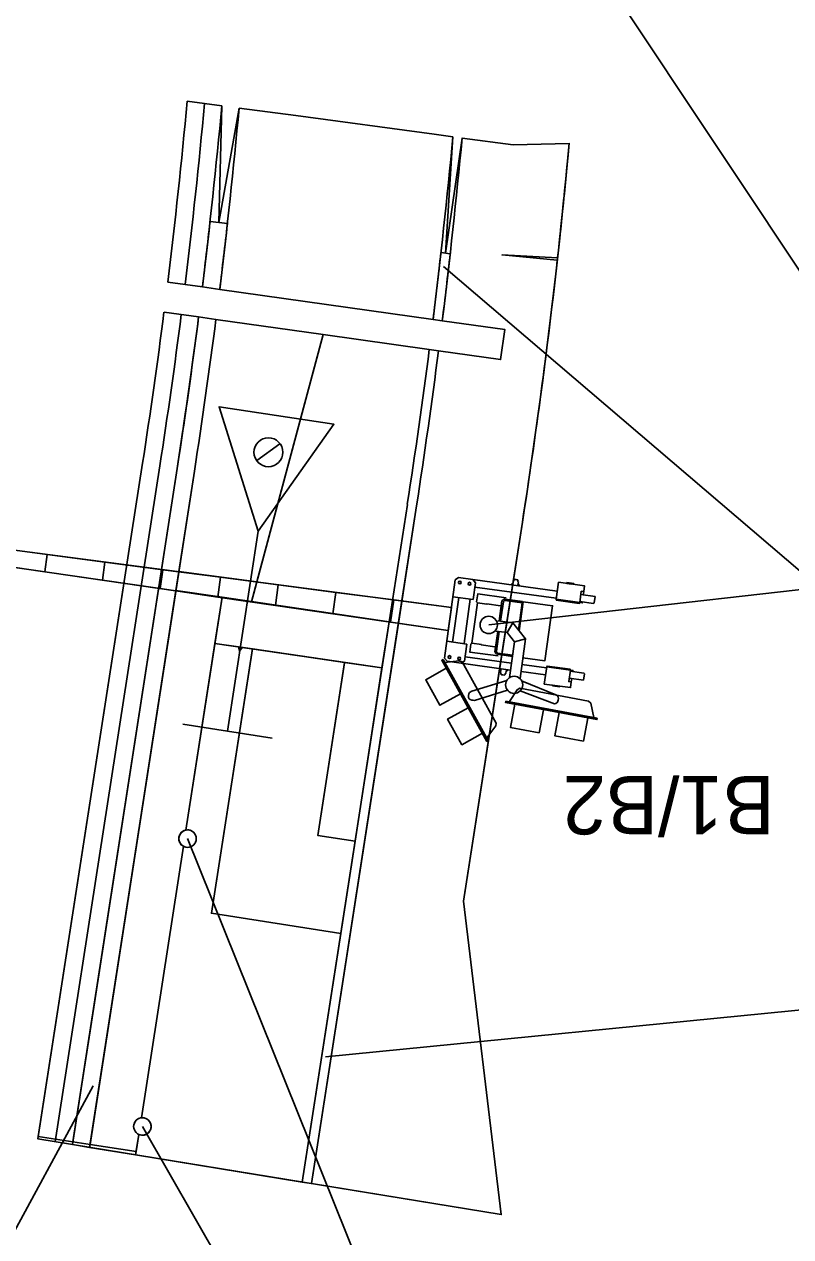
# Model space of a CAD drawing. Extents: x -728547 to -728179, y -1073068 to -1072839.
# Drawn here: x -728503.68 to -728497.09, y -1073053.69 to -1073043.28 of the extents above; entities that cross this region are included whole.
import ezdxf

# ---------------------------------------------------------------- set-up
doc = ezdxf.new("R2010")
doc.units = 0
for name, color, linetype in [('_NOR-návrh tenká', 7, 'Continuous'), ('_NOR-popis', 7, 'Continuous'), ('_NOR-VDZ', 7, 'Continuous'), ('_NOR-šraf_+6', 7, 'Continuous'), ('_NOR-šraf_bezbariéra', 7, 'Continuous'), ('_NOR-šraf_chodník', 7, 'Continuous'), ('_NOR-šraf_signální pás', 7, 'Continuous'), ('_NOR-šraf_varovný pás', 7, 'Continuous'), ('_NOR-šraf_vozovka', 7, 'Continuous'), ('_NOR-šraf_zeleň', 7, 'Continuous'), ('KOS_kabelová trasa', 7, 'Continuous'), ('KOS_nové prvky PZZ', 7, 'Continuous'), ('KTA_PZZ rušené', 7, 'Continuous')]:
    doc.layers.add(name, color=color, linetype=linetype)

# ---------------------------------------------------------------- blocks, each defined once
blk = doc.blocks.new('Závora B')
for p, q in [((0.614, 0.452), (0.676, 0.452)), ((0.676, 0.452), (0.676, 0.445)), ((-0.312, 0.367), (-0.338, 0.343)), ((-0.338, 0.343), (-0.338, -0.335)), ((-0.312, 0.367), (-0.189, 0.367)), ((-0.189, 0.367), (0.541, 0.367)), ((-0.189, 0.367), (-0.163, 0.343)), ((0.769, 0.395), (0.769, 0.367)), ((-0.163, 0.306), (0.541, 0.306)), ((0.259, 0.227), (0.259, -0.009)), ((-6.838, 0.058), (-0.338, 0.104)), ((-0.338, 0.197), (-0.163, 0.197)), ((-0.338, -0.096), (-0.338, 0.104)), ((-0.338, -0.096), (-0.338, 0.104)), ((-0.338, -0.096), (-0.338, 0.104)), ((-0.338, -0.096), (-0.338, 0.104)), ((-0.338, -0.096), (-0.338, 0.104)), ((-0.338, -0.096), (-0.338, 0.104)), ((-0.338, -0.096), (-0.338, 0.104)), ((-0.338, -0.096), (-0.338, 0.104)), ((-0.288, 0.197), (-0.288, -0.188)), ((-0.187, 0.197), (-0.187, -0.188)), ((-0.123, 0.174), (-0.123, -0.176)), ((-6.838, -0.049), (-6.838, 0.058)), ((0.202, 0.045), (0.165, -0.044)), ((-6.838, -0.049), (-0.338, -0.096)), ((0.329, -0.076), (0.239, -0.114)), ((-0.338, -0.188), (-0.163, -0.188)), ((-0.163, -0.188), (-0.163, -0.335)), ((-0.163, -0.298), (0.239, -0.298)), ((0.329, -0.298), (0.541, -0.298)), ((-0.347, -0.347), (0.132, -0.984)), ((-0.312, -0.358), (-0.338, -0.335)), ((-0.189, -0.358), (-0.163, -0.335)), ((-0.189, -0.358), (0.239, -0.358)), ((0.329, -0.358), (0.541, -0.358)), ((0.769, -0.387), (0.769, -0.358)), ((0.653, -0.515), (0.345, -0.438)), ((0.614, -0.443), (0.676, -0.443)), ((0.676, -0.443), (0.676, -0.437)), ((-0.033, -0.659), (0.235, -0.532)), ((0.236, -0.627), (1.032, -0.665))]:
    blk.add_line(p, q)
for points in [[(0.179, 0.418), (0.166, 0.418), (0.165, 0.411), (0.16, 0.411), (0.16, 0.401), (0.157, 0.401), (0.157, 0.378), (0.148, 0.378), (0.148, 0.372), (0.148, 0.367)], [(0.179, 0.418), (0.192, 0.418), (0.193, 0.411), (0.197, 0.411), (0.197, 0.401), (0.201, 0.401), (0.201, 0.378), (0.21, 0.378), (0.21, 0.372), (0.21, 0.367)], [(0.542, 0.445), (0.542, 0.297), (0.747, 0.297), (0.747, 0.395), (0.769, 0.395), (0.769, 0.445), (0.542, 0.445)], [(0.614, 0.452), (0.614, 0.445)], [(0.655, 0.445), (0.614, 0.445)], [(-0.163, 0.343), (-0.163, 0.197)], [(0.872, 0.367), (0.747, 0.367)], [(0.872, 0.367), (0.872, 0.312), (0.866, 0.306), (0.747, 0.306)], [(0.116, 0.251), (-0.13, 0.251), (-0.13, 0.182), (-0.123, 0.174), (-0.04, 0.174), (-0.04, 0.177), (0.077, 0.177), (0.078, 0.181), (0.084, 0.181)], [(0.259, 0.238), (0.109, 0.238), (0.098, 0.236), (0.092, 0.23), (0.086, 0.223), (0.084, 0.219), (0.084, 0.045)], [(0.259, 0.238), (0.259, 0.227), (0.11, 0.227), (0.106, 0.225), (0.102, 0.222), (0.098, 0.218), (0.097, 0.213), (0.097, 0.045)], [(0.265, 0.238), (0.52, 0.238), (0.52, -0.239), (0.329, -0.239)], [(0.265, -0.015), (0.265, 0.238)], [(0.545, 0.297), (0.545, 0.289), (0.745, 0.289), (0.745, 0.297)], [(0.747, 0.297), (0.77, 0.297), (0.77, 0.306)], [(-0.338, -0.096), (-0.338, 0.104), (-0.838, 0.101), (-0.838, -0.092), (-0.338, -0.096)], [(-6.338, -0.053), (-6.338, 0.061), (-6.838, 0.058), (-6.838, -0.049), (-6.338, -0.053)], [(-5.838, -0.057), (-5.838, 0.065), (-6.338, 0.061), (-6.338, -0.053), (-5.838, -0.057)], [(-5.338, -0.06), (-5.338, 0.068), (-5.838, 0.065), (-5.838, -0.057), (-5.338, -0.06)], [(-4.838, -0.064), (-4.838, 0.072), (-5.338, 0.068), (-5.338, -0.06), (-4.838, -0.064)], [(-4.338, -0.067), (-4.338, 0.076), (-4.838, 0.072), (-4.838, -0.064), (-4.338, -0.067)], [(-3.838, -0.071), (-3.838, 0.079), (-4.338, 0.076), (-4.338, -0.067), (-3.838, -0.071)], [(-3.338, -0.074), (-3.338, 0.083), (-3.838, 0.079), (-3.838, -0.071), (-3.338, -0.074)], [(-2.838, -0.078), (-2.838, 0.086), (-3.338, 0.083), (-3.338, -0.074), (-2.838, -0.078)], [(-2.338, -0.082), (-2.338, 0.09), (-2.838, 0.086), (-2.838, -0.078), (-2.338, -0.082)], [(-1.838, -0.085), (-1.838, 0.093), (-2.338, 0.09), (-2.338, -0.082), (-1.838, -0.085)], [(-1.338, -0.089), (-1.338, 0.097), (-1.838, 0.093), (-1.838, -0.085), (-1.338, -0.089)], [(-0.838, -0.092), (-0.838, 0.101), (-1.338, 0.097), (-1.338, -0.089), (-0.838, -0.092)], [(0.071, 0.045), (0.202, 0.045), (0.329, -0.076), (0.329, -0.419)], [(0.066, -0.044), (0.165, -0.044), (0.239, -0.114), (0.239, -0.422)], [(0.239, -0.239), (0.109, -0.239), (0.098, -0.237), (0.092, -0.231), (0.086, -0.224), (0.084, -0.22), (0.084, -0.044)], [(0.239, -0.228), (0.11, -0.228), (0.106, -0.226), (0.102, -0.223), (0.098, -0.219), (0.097, -0.214), (0.097, -0.044)], [(0.116, -0.253), (-0.13, -0.253), (-0.13, -0.184), (-0.123, -0.176), (-0.04, -0.176), (-0.04, -0.178), (0.077, -0.178), (0.078, -0.182), (0.084, -0.182)], [(0.542, -0.437), (0.542, -0.288), (0.747, -0.288), (0.747, -0.387), (0.769, -0.387), (0.769, -0.437), (0.542, -0.437)], [(0.545, -0.288), (0.545, -0.281), (0.745, -0.281), (0.745, -0.288)], [(0.747, -0.288), (0.77, -0.288), (0.77, -0.298)], [(0.872, -0.358), (0.872, -0.304), (0.866, -0.298), (0.747, -0.298)], [(-0.347, -0.347), (-0.358, -0.355), (0.121, -0.992), (0.132, -0.984)], [(-0.329, -0.371), (-0.211, -0.34), (-0.184, -0.346), (0.177, -0.826), (0.178, -0.851), (0.115, -0.962)], [(-0.189, -0.358), (-0.312, -0.358)], [(0.179, -0.409), (0.166, -0.409), (0.165, -0.403), (0.16, -0.403), (0.16, -0.393), (0.157, -0.393), (0.157, -0.37), (0.148, -0.37), (0.148, -0.364), (0.148, -0.358)], [(0.179, -0.409), (0.192, -0.409), (0.193, -0.403), (0.197, -0.403), (0.197, -0.393), (0.201, -0.393), (0.201, -0.37), (0.21, -0.37), (0.21, -0.364), (0.21, -0.358)], [(0.872, -0.358), (0.747, -0.358)], [(-0.311, -0.418), (-0.472, -0.54), (-0.321, -0.74), (-0.16, -0.619)], [(-0.066, -0.584), (0.218, -0.451)], [(0.266, -0.628), (0.318, -0.517), (0.339, -0.501), (0.939, -0.53), (0.959, -0.545), (1.004, -0.664)], [(0.655, -0.437), (0.614, -0.437)], [(0.614, -0.443), (0.614, -0.437)], [(0.652, -0.592), (0.663, -0.589), (0.675, -0.576), (0.679, -0.559), (0.679, -0.544), (0.676, -0.532), (0.667, -0.523), (0.665, -0.52), (0.66, -0.518), (0.653, -0.515)], [(-0.066, -0.584), (-0.084, -0.597), (-0.089, -0.61), (-0.089, -0.625), (-0.087, -0.641), (-0.08, -0.65), (-0.07, -0.655), (-0.055, -0.66), (-0.043, -0.659), (-0.033, -0.659)], [(0.652, -0.592), (0.345, -0.523)], [(0.073, -0.929), (-0.088, -1.05), (-0.239, -0.849), (-0.078, -0.728)], [(0.236, -0.627), (0.235, -0.64), (1.031, -0.678), (1.032, -0.665)], [(0.314, -0.644), (0.305, -0.846), (0.555, -0.858), (0.565, -0.656)], [(0.952, -0.675), (0.942, -0.876), (0.692, -0.864), (0.701, -0.663)]]:
    blk.add_lwpolyline(points)
for centre, radius in [((-0.296, 0.327), 0.0119), ((-0.212, 0.328), 0.0119), ((0, 0), 0.0742), ((-0.296, -0.319), 0.0119), ((-0.212, -0.32), 0.0119), ((0.286, -0.479), 0.0735)]:
    blk.add_circle(centre, radius)

msp = doc.modelspace()

# ---------------------------------------------------------------- linework, layer by layer
at = {"layer": '_NOR-návrh tenká'}
for p, q in [((-728501.98, -1073043.98), (-728502.007, -1073044.983)), ((-728502.007, -1073044.983), (-728501.831, -1073044)), ((-728499.996, -1073044.246), (-728500.059, -1073045.246)), ((-728500.059, -1073045.246), (-728499.917, -1073044.257)), ((-728502.081, -1073044.975), (-728501.932, -1073044.991)), ((-728500.098, -1073045.241), (-728500.019, -1073045.25)), ((-728500.544, -1073048.41), (-728502.374, -1073048.141)), ((-728500.605, -1073048.805), (-728502.04, -1073048.595)), ((-728502.07, -1073050.911), (-728501.718, -1073048.639)), ((-728501.157, -1073050.243), (-728500.927, -1073048.761)), ((-728501.157, -1073050.243), (-728500.836, -1073050.293)), ((-728499.581, -1073053.497), (-728499.904, -1073050.807)), ((-728502.07, -1073050.911), (-728500.958, -1073051.084)), ((-728503.263, -1073052.895), (-728503.559, -1073052.847)), ((-728499.581, -1073053.497), (-728503.263, -1073052.895))]:
    msp.add_line(p, q, dxfattribs=at)
for points in [[(-728501.98, -1073043.98), (-728502.278, -1073043.94)], [(-728502.444, -1073045.494), (-728502.147, -1073045.535)], [(-728502.179, -1073045.793), (-728502.476, -1073045.752)], [(-728502.66, -1073047.048), (-728503.559, -1073052.847)], [(-728502.364, -1073047.094), (-728503.263, -1073052.895)], [(-728502.215, -1073047.117), (-728503.115, -1073052.92)], [(-728500.387, -1073047.401), (-728500.529, -1073048.317)], [(-728500.308, -1073047.413), (-728500.45, -1073048.328)], [(-728499.399, -1073047.554), (-728499.54, -1073048.464)], [(-728500.529, -1073048.317), (-728501.289, -1073053.218)], [(-728500.45, -1073048.328), (-728501.21, -1073053.23)], [(-728499.54, -1073048.464), (-728499.904, -1073050.807)], [(-728502.04, -1073048.595), (-728502.288, -1073050.196)], [(-728502.31, -1073050.336), (-728502.671, -1073052.666)], [(-728502.693, -1073052.808), (-728502.721, -1073052.984)]]:
    msp.add_lwpolyline(points, dxfattribs=at)
for centre in [(-728502.274, -1073050.27), (-728502.662, -1073052.74)]:
    msp.add_circle(centre, 0.075, dxfattribs=at)
for radius, start, end in [(49.7, 352.9936, 354.795), (50, 352.9876, 354.7803), (50.15, 352.9847, 354.7731), (52, 352.9495, 354.687), (52.08, 352.9481, 354.6834), (53, 351.184, 354.726), (49.7, 351.184, 352.6939), (50, 351.184, 352.6897), (50.15, 351.184, 352.6876), (52, 351.184, 352.663), (52.08, 351.184, 352.662)]:
    msp.add_arc((-728551.773, -1073039.431), radius, start, end, dxfattribs=at)
at = {"layer": '_NOR-popis'}
for p, q in [((-728493.062, -1073051.347), (-728499.767, -1073041.269)), ((-728493.062, -1073051.347), (-728500.078, -1073045.361)), ((-728498.014, -1073060.847), (-728502.274, -1073050.27)), ((-728493.062, -1073051.347), (-728501.089, -1073052.144)), ((-728507.112, -1073059.822), (-728503.085, -1073052.392)), ((-728502.662, -1073052.74), (-728498.014, -1073060.847))]:
    msp.add_line(p, q, dxfattribs=at)
at = {"layer": '_NOR-VDZ'}
msp.add_lwpolyline([(-728502.512, -1073047.071), (-728503.411, -1073052.871)], dxfattribs=at)
for start, end in [(352.9906, 354.7876), (351.184, 352.6918)]:
    msp.add_arc((-728551.773, -1073039.431), 49.85, start, end, dxfattribs=at)
at = {"layer": '_NOR-šraf_+6'}
for p, q in [((-728500.019, -1073045.25), (-728500.098, -1073045.241)), ((-728500.166, -1073045.814), (-728500.087, -1073045.825)), ((-728500.119, -1073046.083), (-728500.199, -1073046.072))]:
    msp.add_line(p, q, dxfattribs=at)
msp.add_lwpolyline([(-728500.387, -1073047.401), (-728500.544, -1073048.41), (-728500.605, -1073048.805), (-728500.836, -1073050.293), (-728500.958, -1073051.084), (-728501.289, -1073053.218), (-728501.21, -1073053.231), (-728500.308, -1073047.413)], dxfattribs=at)
for radius, start, end in [(52, 352.9495, 353.5851), (52.08, 352.9481, 353.5851), (52, 351.184, 352.663), (52.08, 351.184, 352.662)]:
    msp.add_arc((-728551.773, -1073039.431), radius, start, end, dxfattribs=at)
at = {"layer": '_NOR-šraf_bezbariéra'}
for p, q in [((-728502.081, -1073044.975), (-728501.932, -1073044.991)), ((-728501.998, -1073045.556), (-728502.147, -1073045.535)), ((-728502.031, -1073045.814), (-728502.179, -1073045.793)), ((-728502.364, -1073047.094), (-728503.259, -1073052.871)), ((-728503.111, -1073052.894), (-728502.215, -1073047.117)), ((-728503.111, -1073052.894), (-728503.259, -1073052.871)), ((-728503.259, -1073052.871), (-728503.111, -1073052.894))]:
    msp.add_line(p, q, dxfattribs=at)
for points in [[(-728503.259, -1073052.871), (-728503.263, -1073052.895), (-728503.229, -1073052.901)], [(-728503.229, -1073052.901), (-728503.115, -1073052.92), (-728503.111, -1073052.894)]]:
    msp.add_lwpolyline(points, dxfattribs=at)
for radius, start, end in [(50, 352.9876, 353.6344), (50.15, 352.9847, 353.6344), (50, 351.184, 352.6897), (50.15, 351.184, 352.6876)]:
    msp.add_arc((-728551.773, -1073039.431), radius, start, end, dxfattribs=at)
at = {"layer": '_NOR-šraf_chodník'}
for p, q in [((-728500.166, -1073045.814), (-728501.998, -1073045.556)), ((-728501.724, -1073048.237), (-728501.111, -1073045.944)), ((-728501.111, -1073045.944), (-728500.199, -1073046.072)), ((-728502.215, -1073047.117), (-728502.349, -1073047.977)), ((-728500.387, -1073047.401), (-728500.544, -1073048.41)), ((-728501.678, -1073048.065), (-728502.349, -1073047.977)), ((-728502.349, -1073047.977), (-728501.678, -1073048.065)), ((-728501.724, -1073048.237), (-728501.678, -1073048.065)), ((-728500.544, -1073048.41), (-728501.724, -1073048.237)), ((-728502.288, -1073050.196), (-728502.04, -1073048.595)), ((-728502.04, -1073048.595), (-728501.838, -1073048.624)), ((-728501.718, -1073048.642), (-728502.07, -1073050.911)), ((-728501.838, -1073048.624), (-728501.827, -1073048.662)), ((-728501.827, -1073048.662), (-728501.838, -1073048.624)), ((-728501.838, -1073048.624), (-728501.804, -1073048.629)), ((-728501.827, -1073048.662), (-728501.804, -1073048.629)), ((-728501.804, -1073048.629), (-728501.827, -1073048.662)), ((-728501.804, -1073048.629), (-728501.718, -1073048.642)), ((-728502.671, -1073052.666), (-728502.31, -1073050.336)), ((-728502.07, -1073050.911), (-728500.958, -1073051.084)), ((-728500.958, -1073051.084), (-728501.289, -1073053.218)), ((-728502.721, -1073052.984), (-728502.693, -1073052.808)), ((-728501.289, -1073053.218), (-728502.721, -1073052.984))]:
    msp.add_line(p, q, dxfattribs=at)
for points in [[(-728501.831, -1073044), (-728501.345, -1073044.065), (-728500.156, -1073044.225), (-728499.996, -1073044.246)], [(-728501.678, -1073048.065), (-728501.111, -1073045.944), (-728502.031, -1073045.814)], [(-728502.349, -1073047.977), (-728502.374, -1073048.141), (-728501.724, -1073048.237)], [(-728501.157, -1073050.243), (-728500.836, -1073050.293), (-728500.605, -1073048.805), (-728500.927, -1073048.758), (-728501.157, -1073050.243)]]:
    msp.add_lwpolyline(points, dxfattribs=at)
for centre, radius, start, end in [((-728551.773, -1073039.431), 50.15, 352.9847, 354.7731), ((-728551.773, -1073039.431), 52, 352.9495, 354.687), ((-728551.773, -1073039.431), 50.15, 351.184, 352.6876), ((-728551.773, -1073039.431), 52, 351.184, 352.663), ((-728502.274, -1073050.27), 0.075, 241.7127, 100.6552), ((-728502.662, -1073052.74), 0.075, 245.3796, 96.9883)]:
    msp.add_arc(centre, radius, start, end, dxfattribs=at)
at = {"layer": '_NOR-šraf_signální pás'}
msp.add_lwpolyline([(-728500.958, -1073051.084), (-728500.836, -1073050.293), (-728501.157, -1073050.243), (-728500.927, -1073048.758), (-728501.718, -1073048.642), (-728502.07, -1073050.911), (-728500.958, -1073051.084)], dxfattribs=at)
at = {"layer": '_NOR-šraf_varovný pás'}
for p, q in [((-728503.111, -1073052.894), (-728502.374, -1073048.141)), ((-728502.374, -1073048.141), (-728501.978, -1073048.199)), ((-728501.978, -1073048.199), (-728502.288, -1073050.196)), ((-728502.31, -1073050.336), (-728502.671, -1073052.666)), ((-728502.693, -1073052.808), (-728502.716, -1073052.955)), ((-728502.716, -1073052.955), (-728503.111, -1073052.894))]:
    msp.add_line(p, q, dxfattribs=at)
for points in [[(-728501.718, -1073048.642), (-728500.605, -1073048.805), (-728500.544, -1073048.41), (-728501.978, -1073048.199), (-728502.04, -1073048.595), (-728501.718, -1073048.642)], [(-728503.111, -1073052.894), (-728502.716, -1073052.955), (-728502.721, -1073052.984), (-728503.115, -1073052.92), (-728503.111, -1073052.894)]]:
    msp.add_lwpolyline(points, dxfattribs=at)
for centre, start, end in [((-728502.274, -1073050.27), 100.6552, 241.7127), ((-728502.662, -1073052.74), 96.9883, 245.3796)]:
    msp.add_arc(centre, 0.075, start, end, dxfattribs=at)
at = {"layer": '_NOR-šraf_vozovka'}
for p, q in [((-728502.476, -1073045.752), (-728502.179, -1073045.793)), ((-728503.556, -1073052.825), (-728502.66, -1073047.048))]:
    msp.add_line(p, q, dxfattribs=at)
for points in [[(-728501.98, -1073043.98), (-728502.278, -1073043.94)], [(-728502.444, -1073045.494), (-728502.147, -1073045.535)], [(-728502.364, -1073047.094), (-728503.106, -1073051.882), (-728503.259, -1073052.871), (-728503.556, -1073052.825)], [(-728503.263, -1073052.895), (-728503.559, -1073052.847), (-728503.556, -1073052.825), (-728503.259, -1073052.871), (-728503.263, -1073052.895)]]:
    msp.add_lwpolyline(points, dxfattribs=at)
for radius, start, end in [(49.7, 352.9936, 354.795), (50, 352.9876, 354.7803), (49.7, 351.184, 352.6939), (50, 351.5451, 352.6897), (50, 351.184, 351.5451)]:
    msp.add_arc((-728551.773, -1073039.431), radius, start, end, dxfattribs=at)
at = {"layer": '_NOR-šraf_zeleň'}
for points in [[(-728499.917, -1073044.257), (-728499.477, -1073044.316), (-728498.997, -1073044.303)], [(-728499.097, -1073045.284), (-728499.574, -1073045.26), (-728499.1, -1073045.306)], [(-728500.119, -1073046.083), (-728499.586, -1073046.158), (-728499.55, -1073045.9), (-728500.087, -1073045.825)], [(-728499.399, -1073047.554), (-728499.904, -1073050.807), (-728499.581, -1073053.497), (-728501.21, -1073053.231), (-728500.308, -1073047.413)]]:
    msp.add_lwpolyline(points, dxfattribs=at)
for radius, start, end in [(52.08, 352.9481, 354.6834), (53, 353.6604, 354.726), (53, 351.184, 353.6355), (52.08, 351.184, 352.662)]:
    msp.add_arc((-728551.773, -1073039.431), radius, start, end, dxfattribs=at)
at = {"layer": 'KOS_kabelová trasa'}
msp.add_lwpolyline([(-728499.688, -1073048.436), (-728495.793, -1073047.995), (-728494.829, -1073039.422)], dxfattribs=at)
at = {"layer": 'KTA_PZZ rušené'}
for p, q in [((-728501.68, -1073047.026), (-728501.481, -1073046.882)), ((-728502.316, -1073049.289), (-728501.548, -1073049.409))]:
    msp.add_line(p, q, dxfattribs=at)
msp.add_lwpolyline([(-728501.932, -1073049.349), (-728501.669, -1073047.631), (-728502.004, -1073046.564), (-728501.017, -1073046.713), (-728501.669, -1073047.631)], dxfattribs=at)
msp.add_circle((-728501.58, -1073046.954), 0.124, dxfattribs=at)
msp.add_circle((-728501.58, -1073046.954), 0.124, dxfattribs=at)

# ---------------------------------------------------------------- block references
at = {"layer": 'KOS_nové prvky PZZ', "rotation": -7.8702938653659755}
msp.add_blockref('Závora B', (-728499.688, -1073048.436), dxfattribs=at)

# ---------------------------------------------------------------- texts
at = {"layer": 'KOS_nové prvky PZZ'}
msp.add_text('B1/B2', height=0.5, rotation=180, dxfattribs=at).set_placement((-728497.232, -1073049.733))

doc.saveas('drawing.dxf')
